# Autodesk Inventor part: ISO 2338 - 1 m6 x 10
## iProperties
Created: 2004-01
Part Number: ISO 2338 - 1 m6 x 10
Material: Standard
Catalog Web Link: file:///C:/Programme/Autodesk/Inventor 5.3/Content/Din/index.htm?doNavigateId=DF12217B-CB3D-11D4-A9FB-0080AD303E0A|5F32AEE2B0DC11D4BA6900C04F798F98|true
Description: Zylinderstift
Document SubType Name: Standard Catalog Part
Standard: ISO 2338 - 1 m6 x 10
Designer: Ulrich
Control State: 0
Master: False
Checked Out: False
Shininess: 20.0
Angle Display Precision: 2
Document Length Units: 11269
Document Angle Units: 11279
Document Time Units: 11290
Document Mass Units: 11283
Document Length Units Precision: 3
Document Angle Units Precision: 2
Compacted: True
KLASSIFIKATION: 31163203 un/spsc
HERSTELLER: DIN Normsystem
Density: 0.0
Volumn: 0.0
Area: 0.0
PropertySet Name: Model Information
Author: Ulrich
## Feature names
1. Basis1
